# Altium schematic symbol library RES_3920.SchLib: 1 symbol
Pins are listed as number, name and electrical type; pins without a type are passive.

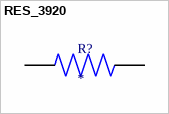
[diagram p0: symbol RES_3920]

## RES_3920
designator R?
1 mOhms Â±1% 8W Chip Resistor 3920 (1052 Metric) Automotive AEC-Q200, Current Sense Metal Element; MF: Rohm; MP: PSR400ITQFH1L00
footprint RES_3920
pins: 1, 2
